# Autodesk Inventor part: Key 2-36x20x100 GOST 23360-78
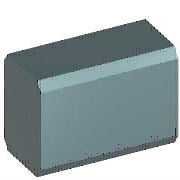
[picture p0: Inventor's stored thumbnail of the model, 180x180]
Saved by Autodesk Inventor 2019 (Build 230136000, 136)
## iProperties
Created: 2018-01
Part Number: Key 2-36x20x100 GOST 23360-78
Material: Steel, Mild
Description: Keyed joints with sunk keys
Document SubType Name: Modeling
Standard: GOST 23360-78 (2)
Designer: m.vorobev
Standards Organization: GOST
Language: en-US
Size Designation: 36 x 20 x 100
Categories: <MemberInstance><Categories><Category DisplayName="Shaft Parts" InternalName="7f7aeb1f-a693-4053-b835-cee3144e0d98" Mnemonic="SHFT"><Category DisplayName="Keys"
Density: 7.85 g/cm^3
Appearance: Semi-Polished
IsCustomPart: 1
Author: m.vorobev
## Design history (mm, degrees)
sketch "Sketch1"
  geometry: L1 (18, 18)-(118, 18); L2 (118, 18)-(118, -18); L3 (118, -18)-(18, -18); L4 (0, 7)-(0, -7) reference; L5 (-6, 0)-(36, 0) reference; L6 (18, 18)-(18, -18); A1 r 18 centre (18, 0) between (18, 18) and (18, -18)
  constraints: 8 end point, 3 tangent, 2 perpendicular, 2 point on circle, 1 centre point, 1 horizontal, 1 parallel, 1 point on line
  dimensions: "d0" = 18 radius of A1 (= 0.5 x PB); "d19" = 100 distance of L1.start L1.end (= NLG)
extrude "Body1" new body sketch "Sketch1" taper "d3" = 0 deg; stored distance "d4" = 10
body "Solid1"
workplane "Work Plane1"
workplane "Work Plane2"
chamfer "Chamfer1" distance "d8" = 1 (= PHH); stored, may be unused: second distance "d9" = 1 (= PHH), angle "d13" = 45 deg
other parameters: "d1" = -12 (= -PNT), "d2" = 8 (= PH - PNT), "NLG" = 100 [user parameter; used in 1 equation term], "PB" = 36 [user parameter; used in 1 equation term], "PNT" = 12 [user parameter; used in 2 equation terms], "PHH" = 1 [user parameter; used in 2 equation terms], "d10" = 0, "d16" = 0, "d17" = 0, "d18" = 0, "RR" = 0.7 [user parameter], "PLB1" = 118 [user parameter], "PLB2" = 136 [user parameter], "PUEB" = 8.4 [user parameter]
